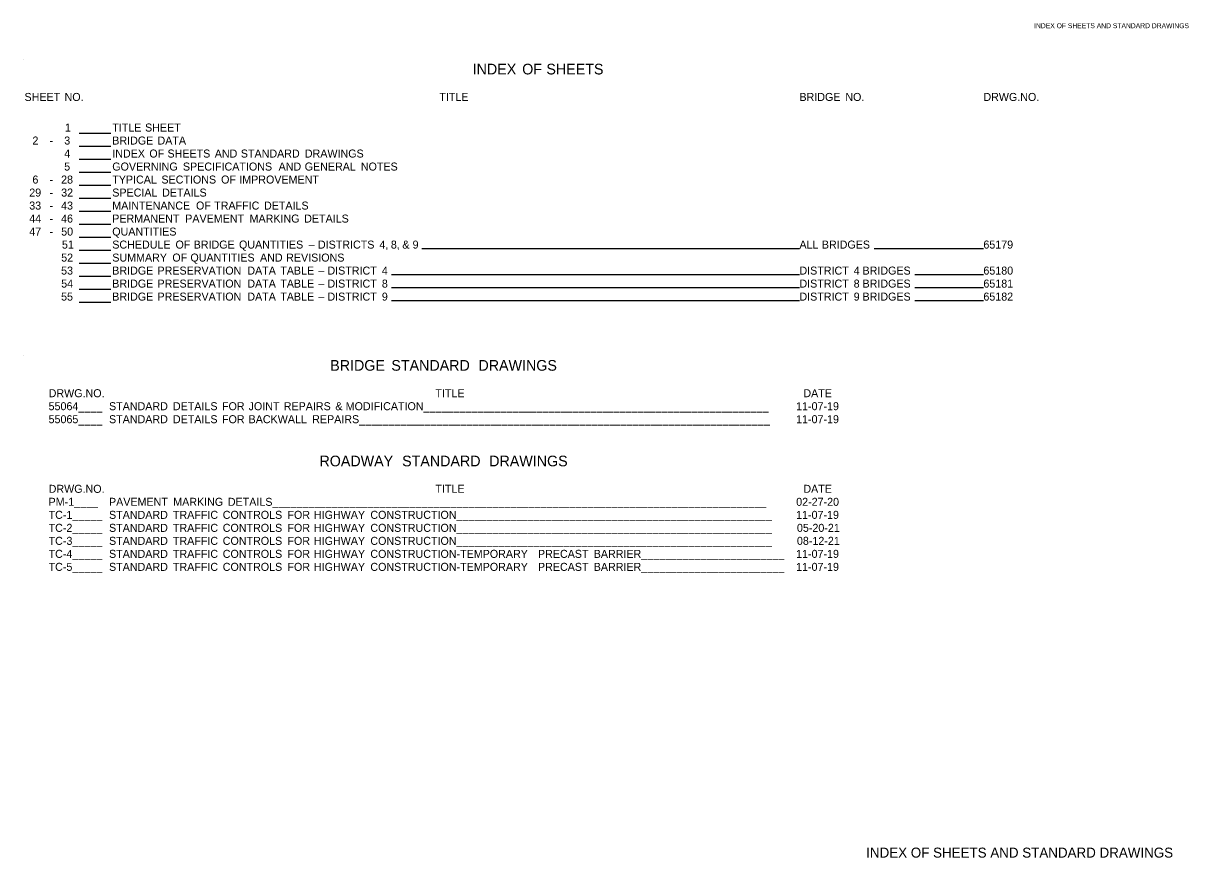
# Model space of a CAD drawing. Extents: x 1930556 to 1931949, y 596452 to 599561.
import ezdxf

# ---------------------------------------------------------------- set-up
doc = ezdxf.new("R2010")
doc.units = 0
for name, color, linetype in [('Default', 7, 'Continuous'), ('R_Border', 7, 'Continuous'), ('S_AREA_CALC', 7, 'Continuous')]:
    doc.layers.add(name, color=color, linetype=linetype)

msp = doc.modelspace()

# ---------------------------------------------------------------- linework, layer by layer
at = {"layer": 'Default'}
for p, q in [((1930556.1, 599518), (1930556.1, 599518)), ((1930623.2, 599429.1), (1930661.4, 599429.1)), ((1930623.2, 599413.5), (1930661.4, 599413.5)), ((1930623.2, 599397.9), (1930661.4, 599397.9)), ((1930623.2, 599382.3), (1930661.4, 599382.3)), ((1930623.2, 599366.7), (1930661.4, 599366.7)), ((1930623.2, 599351.1), (1930661.4, 599351.1)), ((1930623.2, 599335.5), (1930661.4, 599335.5)), ((1930623.2, 599319.9), (1930661.4, 599319.9)), ((1930623.2, 599304.3), (1930661.4, 599304.3)), ((1931034.4, 599290.8), (1931487.5, 599290.8)), ((1931577.1, 599290.8), (1931708.2, 599290.8)), ((1930623.2, 599288.7), (1930661.4, 599288.7)), ((1930623.2, 599273.1), (1930661.4, 599273.1)), ((1930623.2, 599257.5), (1930661.4, 599257.5)), ((1930997.9, 599259.6), (1931487.5, 599259.6)), ((1931626, 599259.6), (1931708.2, 599259.6)), ((1930623.2, 599241.9), (1930661.4, 599241.9)), ((1930997.9, 599244), (1931487.5, 599244)), ((1931626, 599244), (1931708.2, 599244)), ((1930623.2, 599226.3), (1930661.4, 599226.3)), ((1930997.9, 599228.4), (1931487.5, 599228.4)), ((1931626, 599228.4), (1931708.2, 599228.4)), ((1930556.1, 599162.6), (1930556.1, 599162.6))]:
    msp.add_line(p, q, dxfattribs=at)

# ---------------------------------------------------------------- texts
for s, height, p in [('INDEX', 12.8, (1931095.4, 599499.5)), (' OF', 12.8, (1931150.1, 599499.5)), (' SHEETS', 12.8, (1931179.1, 599499.5)), ('SHEET', 9.6, (1930557.7, 599467.7)), (' NO.', 9.6, (1930602.2, 599467.7)), ('TITLE', 9.6, (1931055.4, 599467.7)), ('BRIDGE', 9.6, (1931487.5, 599467.7)), (' NO.', 9.6, (1931539, 599467.7)), ('DRWG.NO.', 9.6, (1931708.2, 599467.7)), ('1', 9.6, (1930606.3, 599431)), ('TITLE', 9.6, (1930663, 599431)), (' SHEET', 9.6, (1930698.8, 599431)), ('2', 9.6, (1930567.2, 599415.4)), ('-', 9.6, (1930587.7, 599415.4)), ('3', 9.6, (1930605.4, 599415.4)), ('BRIDGE', 9.6, (1930663, 599415.4)), (' DATA', 9.6, (1930713.7, 599415.4)), ('4', 9.6, (1930605.4, 599399.8)), ('INDEX', 9.6, (1930663, 599399.8)), (' OF', 9.6, (1930703.9, 599399.8)), (' SHEETS', 9.6, (1930725.7, 599399.8)), (' AND', 9.6, (1930782.4, 599399.8)), (' STANDARD', 9.6, (1930813.7, 599399.8)), (' DRAWINGS', 9.6, (1930890.5, 599399.8)), ('5', 9.6, (1930605.3, 599384.2)), ('GOVERNING', 9.6, (1930663, 599384.2)), (' SPECIFICATIONS', 9.6, (1930744.2, 599384.2)), (' AND', 9.6, (1930859, 599384.2)), (' GENERAL', 9.6, (1930890.3, 599384.2)), (' NOTES', 9.6, (1930957.7, 599384.2)), ('6', 9.6, (1930567.2, 599368.6)), ('28', 9.6, (1930601.6, 599368.6)), ('TYPICAL', 9.6, (1930663, 599368.6)), (' SECTIONS', 9.6, (1930718.4, 599368.6)), (' OF', 9.6, (1930790, 599368.6)), (' IMPROVEMENT', 9.6, (1930811.8, 599368.6)), ('29', 9.6, (1930563.4, 599353)), ('-', 9.6, (1930587.7, 599368.6)), ('32', 9.6, (1930601.7, 599353)), ('SPECIAL', 9.6, (1930663, 599353)), (' DETAILS', 9.6, (1930719.2, 599353)), ('33', 9.6, (1930563.4, 599337.4)), ('-', 9.6, (1930587.7, 599353)), ('43', 9.6, (1930601.6, 599337.4)), ('MAINTENANCE', 9.6, (1930663, 599337.4)), (' OF', 9.6, (1930759.9, 599337.4)), (' TRAFFIC', 9.6, (1930781.7, 599337.4)), (' DETAILS', 9.6, (1930841.5, 599337.4)), ('-', 9.6, (1930587.7, 599337.4)), ('44', 9.6, (1930563.4, 599321.8)), ('-', 9.6, (1930587.7, 599321.8)), ('46', 9.6, (1930601.6, 599321.8)), ('PERMANENT', 9.6, (1930663, 599321.8)), (' PAVEMENT', 9.6, (1930747, 599321.8)), (' MARKING', 9.6, (1930824.2, 599321.8)), (' DETAILS', 9.6, (1930889.7, 599321.8)), ('47', 9.6, (1930563.4, 599306.2)), ('-', 9.6, (1930587.7, 599306.2)), ('50', 9.6, (1930601.7, 599306.2)), ('QUANTITIES', 9.6, (1930663, 599306.2)), ('51', 9.6, (1930602.6, 599290.6)), ('SCHEDULE', 9.6, (1930663, 599290.6)), (' OF', 9.6, (1930735.3, 599290.6)), (' BRIDGE', 9.6, (1930757.1, 599290.6)), (' QUANTITIES', 9.6, (1930811.5, 599290.6)), ('–', 9.6, (1930898.8, 599290.6)), (' DISTRICTS', 9.6, (1930906.2, 599290.6)), (' 4,', 9.6, (1930980, 599290.6)), (' 8,', 9.6, (1930993.7, 599290.6)), (' &', 9.6, (1931007.4, 599290.6)), (' 9', 9.6, (1931019.8, 599290.6)), ('ALL', 9.6, (1931487.5, 599290.6)), (' BRIDGES', 9.6, (1931510.8, 599290.6)), ('65179', 9.6, (1931708.2, 599290.6)), ('52', 9.6, (1930601.7, 599275)), ('SUMMARY', 9.6, (1930663, 599275)), (' OF', 9.6, (1930731.5, 599275)), (' QUANTITIES', 9.6, (1930753.2, 599275)), (' AND', 9.6, (1930836.7, 599275)), (' REVISIONS', 9.6, (1930868.1, 599275)), ('53', 9.6, (1930601.6, 599259.4)), ('BRIDGE', 9.6, (1930663, 599259.4)), (' PRESERVATION', 9.6, (1930713.7, 599259.4)), (' DATA', 9.6, (1930821.5, 599259.4)), (' TABLE', 9.6, (1930861, 599259.4)), ('–', 9.6, (1930910.2, 599259.4)), (' DISTRICT', 9.6, (1930917.6, 599259.4)), (' 4', 9.6, (1930982.9, 599259.4)), ('DISTRICT', 9.6, (1931487.5, 599259.4)), (' 4', 9.6, (1931549, 599259.4)), (' BRIDGES', 9.6, (1931559.6, 599259.4)), ('65180', 9.6, (1931708.2, 599259.4)), ('54', 9.6, (1930601.7, 599243.8)), ('BRIDGE', 9.6, (1930663, 599243.8)), (' PRESERVATION', 9.6, (1930713.7, 599243.8)), (' DATA', 9.6, (1930821.5, 599243.8)), (' TABLE', 9.6, (1930861, 599243.8)), (' DISTRICT', 9.6, (1930917.6, 599243.8)), (' 8', 9.6, (1930982.9, 599243.8)), ('DISTRICT', 9.6, (1931487.5, 599243.8)), (' 8', 9.6, (1931549, 599243.8)), (' BRIDGES', 9.6, (1931559.6, 599243.8)), ('65181', 9.6, (1931708.2, 599243.8)), ('55', 9.6, (1930601.6, 599228.2)), ('BRIDGE', 9.6, (1930663, 599228.2)), (' PRESERVATION', 9.6, (1930713.7, 599228.2)), (' DATA', 9.6, (1930821.5, 599228.2)), (' TABLE', 9.6, (1930861, 599228.2)), ('–', 9.6, (1930910.2, 599243.8)), (' DISTRICT', 9.6, (1930917.6, 599228.2)), (' 9', 9.6, (1930982.9, 599228.2)), ('DISTRICT', 9.6, (1931487.5, 599228.2)), (' 9', 9.6, (1931549, 599228.2)), (' BRIDGES', 9.6, (1931559.6, 599228.2)), ('65182', 9.6, (1931708.2, 599228.2)), ('–', 9.6, (1930910.2, 599228.2)), ('BRIDGE', 12.8, (1930924.5, 599144.1)), (' STANDARD', 12.8, (1930993.1, 599144.1)), (' DRAWINGS', 12.8, (1931097.6, 599144.1)), ('DRWG.NO.', 9.6, (1930586.7, 599112.3)), ('TITLE', 9.6, (1931050.7, 599112.3)), ('DATE', 9.6, (1931492.2, 599112.3)), ('55064____', 9.6, (1930586.6, 599096.7)), ('STANDARD', 9.6, (1930659.1, 599096.7)), (' DETAILS', 9.6, (1930732.2, 599096.7)), (' FOR', 9.6, (1930791.1, 599096.7)), (' JOINT', 9.6, (1930823, 599096.7)), (' REPAIRS', 9.6, (1930865.2, 599096.7)), (' &', 9.6, (1930927.1, 599096.7)), (' MODIFICATION__________________________________________________________', 9.6, (1930939.5, 599096.7)), ('11-07-19', 9.6, (1931483.5, 599096.7)), ('55065____', 9.6, (1930586.6, 599081.1)), ('STANDARD', 9.6, (1930659.1, 599081.1)), (' DETAILS', 9.6, (1930732.2, 599081.1)), (' FOR', 9.6, (1930791.1, 599081.1)), (' BACKWALL', 9.6, (1930823, 599081.1)), (' REPAIRS_____________________________________________________________________', 9.6, (1930899.3, 599081.1)), ('11-07-19', 9.6, (1931483.5, 599081.1)), ('ROADWAY', 12.8, (1930911.6, 599029.4)), (' STANDARD', 12.8, (1931006, 599029.4)), (' DRAWINGS', 12.8, (1931110.5, 599029.4)), ('DRWG.NO.', 9.6, (1930586.7, 598997.6)), ('TITLE', 9.6, (1931050.7, 598997.6)), ('DATE', 9.6, (1931492.2, 598997.6)), ('PM-1____', 9.6, (1930586.6, 598982)), ('PAVEMENT', 9.6, (1930659.1, 598982)), (' MARKING', 9.6, (1930732.6, 598982)), (' DETAILS___________________________________________________________________________________', 9.6, (1930798.1, 598982)), ('02-27-20', 9.6, (1931483.6, 598982)), ('TC-1_____', 9.6, (1930586.6, 598966.4)), ('STANDARD', 9.6, (1930659.1, 598966.4)), (' TRAFFIC', 9.6, (1930732.2, 598966.4)), (' CONTROLS', 9.6, (1930792, 598966.4)), (' FOR', 9.6, (1930869.6, 598966.4)), (' HIGHWAY', 9.6, (1930901.4, 598966.4)), (' CONSTRUCTION_____________________________________________________', 9.6, (1930969.1, 598966.4)), ('11-07-19', 9.6, (1931483.5, 598966.4)), ('TC-2_____', 9.6, (1930586.6, 598950.8)), ('STANDARD', 9.6, (1930659.1, 598950.8)), (' TRAFFIC', 9.6, (1930732.2, 598950.8)), (' CONTROLS', 9.6, (1930792, 598950.8)), (' FOR', 9.6, (1930869.6, 598950.8)), (' HIGHWAY', 9.6, (1930901.4, 598950.8)), (' CONSTRUCTION_____________________________________________________', 9.6, (1930969.1, 598950.8)), ('05-20-21', 9.6, (1931484.5, 598950.8)), ('TC-3_____', 9.6, (1930586.6, 598935.2)), ('STANDARD', 9.6, (1930659.1, 598935.2)), (' TRAFFIC', 9.6, (1930732.2, 598935.2)), (' CONTROLS', 9.6, (1930792, 598935.2)), (' FOR', 9.6, (1930869.6, 598935.2)), (' HIGHWAY', 9.6, (1930901.4, 598935.2)), (' CONSTRUCTION_____________________________________________________', 9.6, (1930969.1, 598935.2)), ('08-12-21', 9.6, (1931484.5, 598935.2)), ('TC-4_____', 9.6, (1930586.6, 598919.6)), ('STANDARD', 9.6, (1930659.1, 598919.6)), (' TRAFFIC', 9.6, (1930732.2, 598919.6)), (' CONTROLS', 9.6, (1930792, 598919.6)), (' FOR', 9.6, (1930869.6, 598919.6)), (' HIGHWAY', 9.6, (1930901.4, 598919.6)), (' CONSTRUCTION-TEMPORARY', 9.6, (1930969.1, 598919.6)), (' PRECAST', 9.6, (1931170.2, 598919.6)), (' BARRIER________________________', 9.6, (1931237.1, 598919.6)), ('11-07-19', 9.6, (1931483.5, 598919.6)), ('TC-5_____', 9.6, (1930586.6, 598904)), ('STANDARD', 9.6, (1930659.1, 598904)), (' TRAFFIC', 9.6, (1930732.2, 598904)), (' CONTROLS', 9.6, (1930792, 598904)), (' FOR', 9.6, (1930869.6, 598904)), (' HIGHWAY', 9.6, (1930901.4, 598904)), (' CONSTRUCTION-TEMPORARY', 9.6, (1930969.1, 598904)), (' PRECAST', 9.6, (1931170.2, 598904)), (' BARRIER________________________', 9.6, (1931237.1, 598904)), ('11-07-19', 9.6, (1931483.5, 598904))]:
    msp.add_text(s, height=height, rotation=360, dxfattribs=at).set_placement(p)
at = {"layer": 'R_Border'}
msp.add_text('INDEX OF SHEETS AND STANDARD DRAWINGS', height=12, rotation=360, dxfattribs=at).set_placement((1931567.6, 598560))
at = {"layer": 'S_AREA_CALC'}
msp.add_text('INDEX OF SHEETS AND STANDARD DRAWINGS', height=5.862, rotation=360, dxfattribs=at).set_placement((1931769.1, 599555))

doc.saveas('drawing.dxf')
